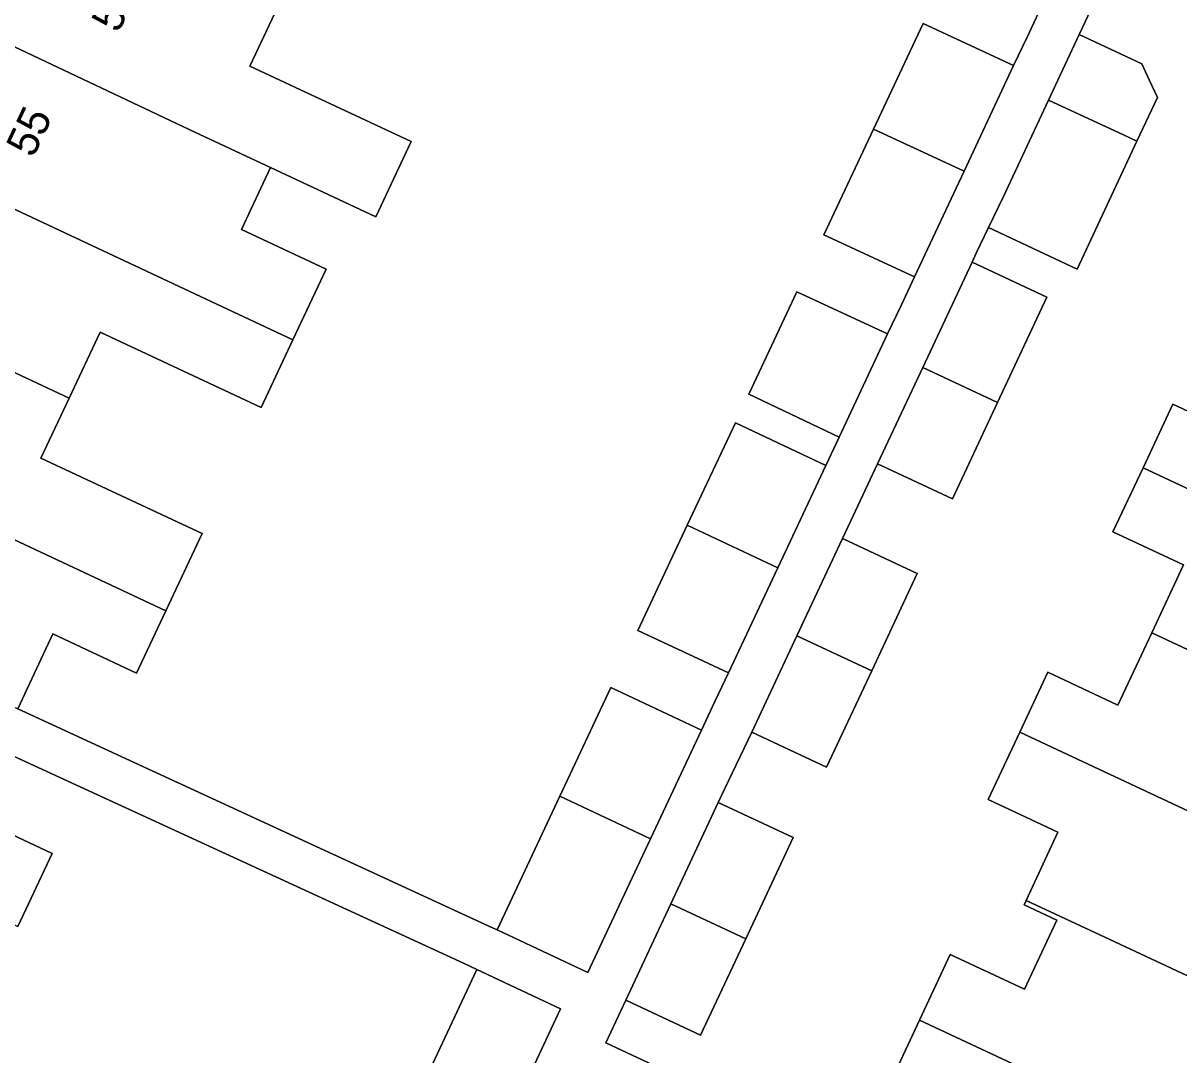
# Model space of a CAD drawing. Extents: x 159817 to 160765, y 380688 to 381638.
# Drawn here: x 160172.67 to 160209.67, y 381387.82 to 381420.86 of the extents above; entities that cross this region are included whole.
import ezdxf

# ---------------------------------------------------------------- set-up
doc = ezdxf.new("R2010")
doc.units = 0
for name, color, linetype in [('IMGEO_Erf', 7, 'Continuous'), ('IMGEO_Pand', 7, 'Continuous'), ('IMGEO_Pand_nummerreeks', 7, 'Continuous'), ('IMGEO_Voetpad_halfverhard', 7, 'Continuous')]:
    doc.layers.add(name, color=color, linetype=linetype)

msp = doc.modelspace()

# ---------------------------------------------------------------- linework, layer by layer
at = {"layer": 'IMGEO_Erf'}
for points in [[(160207.212, 381422.064), (160206.477, 381420.493), (160208.487, 381419.558), (160208.723, 381419.049), (160208.986, 381418.48), (160208.329, 381417.077), (160206.415, 381412.986), (160203.577, 381414.314), (160203.188, 381413.498), (160203.05, 381413.202), (160205.446, 381412.081), (160203.87, 381408.711), (160202.425, 381405.623), (160200.029, 381406.744), (160199.156, 381404.905), (160198.899, 381404.355), (160201.296, 381403.235), (160199.838, 381400.119), (160198.393, 381397.03), (160195.997, 381398.151), (160195.125, 381396.328), (160194.927, 381395.905), (160197.323, 381394.784), (160195.805, 381391.539), (160194.362, 381388.453), (160191.965, 381389.574), (160191.323, 381388.201), (160201.582, 381383.397)], [(160180.728, 381421.182), (160179.932, 381419.485), (160185.093, 381417.065), (160183.961, 381414.653), (160180.593, 381416.233), (160179.661, 381414.248), (160182.373, 381412.976), (160181.311, 381410.713), (160180.295, 381408.546), (160175.138, 381410.964), (160174.146, 381408.849), (160173.247, 381406.931), (160178.406, 381404.511), (160177.244, 381402.034), (160176.309, 381400.04), (160173.627, 381401.298), (160172.502, 381398.901), (160187.702, 381391.888), (160187.848, 381391.819), (160189.859, 381396.102), (160191.493, 381399.581), (160194.393, 381398.22), (160194.821, 381399.132), (160195.252, 381400.05), (160192.352, 381401.411), (160193.933, 381404.779), (160195.476, 381408.063), (160198.371, 381406.694), (160198.799, 381407.605), (160195.904, 381408.974), (160197.446, 381412.259), (160200.348, 381410.906), (160200.778, 381411.822), (160201.206, 381412.733), (160198.304, 381414.086), (160199.893, 381417.469), (160201.481, 381420.852), (160204.383, 381419.5), (160204.811, 381420.411), (160205.24, 381421.324)], [(160200.395, 381386.853), (160201.367, 381388.93), (160202.353, 381391.037), (160204.734, 381389.923), (160205.769, 381392.135), (160204.717, 381392.628), (160204.781, 381392.764), (160205.802, 381394.947), (160203.569, 381395.993), (160204.579, 381398.151), (160205.477, 381400.071), (160207.722, 381399.021), (160208.804, 381401.334), (160209.822, 381403.508), (160207.562, 381404.566), (160208.525, 381406.624), (160209.479, 381408.662), (160211.787, 381407.583)], [(160185.072, 381386.012), (160187.195, 381390.554), (160186.771, 381390.752), (160169.408, 381398.739)], [(160168.448, 381396.692), (160173.607, 381394.272), (160172.508, 381391.928)]]:
    msp.add_lwpolyline(points, dxfattribs=at)
at = {"layer": 'IMGEO_Pand'}
for points in [[(160179.932, 381419.485), (160180.728, 381421.182), (160173.906, 381424.363), (160172.106, 381420.527), (160171.993, 381420.29), (160178.167, 381417.371), (160180.593, 381416.233), (160183.961, 381414.653), (160185.093, 381417.065)], [(160180.593, 381416.233), (160178.167, 381417.371), (160171.993, 381420.29), (160172.106, 381420.527), (160171.409, 381420.854), (160169.297, 381416.351), (160181.311, 381410.713), (160182.373, 381412.976), (160179.661, 381414.248)], [(160204.383, 381419.5), (160201.481, 381420.852), (160199.893, 381417.469), (160202.794, 381416.115)], [(160206.477, 381420.493), (160205.496, 381418.395), (160207.895, 381417.279), (160208.329, 381417.077), (160208.986, 381418.48), (160208.723, 381419.049), (160208.487, 381419.558)], [(160208.329, 381417.077), (160207.895, 381417.279), (160205.496, 381418.395), (160204.053, 381415.31), (160203.577, 381414.314), (160206.415, 381412.986)], [(160202.794, 381416.115), (160199.893, 381417.469), (160198.304, 381414.086), (160201.206, 381412.733)], [(160169.297, 381416.351), (160167.289, 381412.068), (160174.146, 381408.849), (160175.138, 381410.964), (160180.295, 381408.546), (160181.311, 381410.713)], [(160205.446, 381412.081), (160203.05, 381413.202), (160201.472, 381409.829), (160203.87, 381408.711)], [(160200.348, 381410.906), (160197.446, 381412.259), (160195.904, 381408.974), (160198.799, 381407.605)], [(160177.244, 381402.034), (160178.406, 381404.511), (160173.247, 381406.931), (160174.146, 381408.849), (160167.289, 381412.068), (160165.228, 381407.674)], [(160201.472, 381409.829), (160200.029, 381406.744), (160202.425, 381405.623), (160203.87, 381408.711)], [(160212.813, 381409.776), (160211.787, 381407.583), (160209.479, 381408.662), (160208.525, 381406.624), (160220.343, 381401.093), (160222.323, 381405.325), (160215.295, 381408.614)], [(160198.371, 381406.694), (160195.476, 381408.063), (160193.933, 381404.779), (160196.833, 381403.418)], [(160177.244, 381402.034), (160165.228, 381407.674), (160163.167, 381403.278), (160167.694, 381401.155), (160170.054, 381400.048), (160172.502, 381398.901), (160173.627, 381401.298), (160176.309, 381400.04)], [(160218.363, 381396.861), (160220.343, 381401.093), (160208.525, 381406.624), (160207.562, 381404.566), (160209.822, 381403.508), (160208.804, 381401.334), (160211.266, 381400.182)], [(160196.833, 381403.418), (160193.933, 381404.779), (160192.352, 381401.411), (160195.252, 381400.05)], [(160201.296, 381403.235), (160198.899, 381404.355), (160197.44, 381401.237), (160199.838, 381400.119)], [(160160.512, 381397.576), (160172.508, 381391.928), (160173.607, 381394.272), (160168.448, 381396.692), (160169.408, 381398.739), (160167.09, 381399.826), (160162.562, 381401.949)], [(160199.838, 381400.119), (160197.44, 381401.237), (160195.997, 381398.151), (160198.393, 381397.03)], [(160218.363, 381396.861), (160211.266, 381400.182), (160208.804, 381401.334), (160207.722, 381399.021), (160205.477, 381400.071), (160204.579, 381398.151), (160216.382, 381392.628)], [(160194.393, 381398.22), (160191.493, 381399.581), (160189.859, 381396.102), (160192.759, 381394.741)], [(160204.579, 381398.151), (160203.569, 381395.993), (160205.802, 381394.947), (160204.781, 381392.764), (160207.304, 381391.584), (160214.351, 381388.288), (160216.382, 381392.628)], [(160192.759, 381394.741), (160189.859, 381396.102), (160187.848, 381391.819), (160190.748, 381390.458), (160191.754, 381392.6)], [(160197.323, 381394.784), (160194.927, 381395.905), (160193.408, 381392.659), (160195.805, 381391.539)], [(160191.965, 381389.574), (160194.362, 381388.453), (160195.805, 381391.539), (160193.408, 381392.659), (160193.088, 381391.975)], [(160213.096, 381383.444), (160215.179, 381387.898), (160214.351, 381388.288), (160207.304, 381391.584), (160204.781, 381392.764), (160204.717, 381392.628), (160205.769, 381392.135), (160204.734, 381389.923), (160202.353, 381391.037), (160201.367, 381388.93)], [(160189.88, 381389.298), (160187.195, 381390.554), (160185.072, 381386.012), (160187.754, 381384.75)], [(160213.096, 381383.444), (160201.367, 381388.93), (160200.395, 381386.853), (160202.696, 381385.776), (160201.582, 381383.397), (160204.259, 381382.144), (160206.483, 381381.104), (160211.011, 381378.985)]]:
    msp.add_lwpolyline(points, close=True, dxfattribs=at)
at = {"layer": 'IMGEO_Voetpad_halfverhard'}
for points in [[(160201.582, 381383.397), (160191.323, 381388.201), (160191.965, 381389.574), (160193.088, 381391.975), (160193.408, 381392.659), (160194.927, 381395.905), (160195.125, 381396.328), (160195.997, 381398.151), (160197.44, 381401.237), (160198.899, 381404.355), (160199.156, 381404.905), (160200.029, 381406.744), (160201.472, 381409.829), (160203.05, 381413.202), (160203.188, 381413.498), (160203.577, 381414.314), (160204.053, 381415.31), (160205.496, 381418.395), (160206.477, 381420.493), (160207.212, 381422.064)], [(160205.24, 381421.324), (160204.811, 381420.411), (160204.383, 381419.5), (160202.794, 381416.115), (160201.206, 381412.733), (160200.778, 381411.822), (160200.348, 381410.906), (160198.799, 381407.605), (160198.371, 381406.694), (160196.833, 381403.418), (160195.252, 381400.05), (160194.821, 381399.132), (160194.393, 381398.22), (160192.759, 381394.741), (160191.754, 381392.6), (160190.748, 381390.458), (160187.848, 381391.819), (160187.702, 381391.888), (160172.502, 381398.901)], [(160169.408, 381398.739), (160186.771, 381390.752), (160187.195, 381390.554), (160189.88, 381389.298), (160187.754, 381384.75), (160187.457, 381384.115), (160186.216, 381381.46), (160185.79, 381380.55), (160185.365, 381379.64), (160183.765, 381376.218), (160182.235, 381372.943), (160181.8, 381372.013), (160181.373, 381371.1), (160179.755, 381367.64), (160178.224, 381364.363), (160177.754, 381363.358), (160177.357, 381362.509), (160175.752, 381359.075), (160174.197, 381355.748), (160173.75, 381354.793), (160173.321, 381353.876), (160171.748, 381350.511)]]:
    msp.add_lwpolyline(points, dxfattribs=at)

# ---------------------------------------------------------------- texts
at = {"layer": 'IMGEO_Pand_nummerreeks'}
for s, p in [('53', (160175.724, 381420.515)), ('55', (160172.997, 381416.517))]:
    msp.add_text(s, height=1, rotation=64.876, dxfattribs=at).set_placement(p)

doc.saveas('drawing.dxf')
